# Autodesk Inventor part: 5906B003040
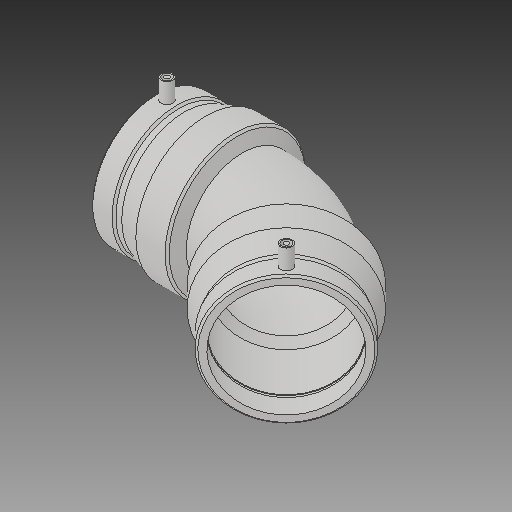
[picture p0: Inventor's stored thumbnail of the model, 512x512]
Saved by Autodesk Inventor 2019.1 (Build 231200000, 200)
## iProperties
Created: 2017-06
Part Number: 5906B003040
Material: Generic
Description: PLASSON 45° ELBOW 4''
Document SubType Name: Modeling
Designer: KIM
Mass: 55.0731 g
Surface Area: 148.067 cm^2
Volume: 55.0731 cm^3
Density: 1 g/cm^3
Appearance: Default
Author: KIM
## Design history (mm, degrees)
derived "5906B.ipt"
feature "Solid1::5906B.ipt"
tag "TaggingFeature1"
body "Solid1"
other parameters: "d_" = 114.1, "L_" = 271.78, "L_1" = 81.026, "D_" = 142.494, "A_" = 85.598, "d_2" = 12, "d2" = 142.494, "d4" = 67.945, "d5" = 128.2446, "d8" = 168 deg, "d10" = 32.4104, "d11" = 10.80347, "d14" = 17.6296, "d18" = 114.1, "d19" = 3.52592, "d20" = 168 deg, "d22" = 131.09448, "d23" = 142.494, "d24" = 127.16165, "d29" = 85.598, "d30" = 15, "d31" = 95.123, "d34" = 5 deg, "d35" = 12, "d39" = 0, "d41" = 4, "d42" = 14, "d43" = 0, "d44" = 9.6, "d45" = 4.8, "d46" = 6, "d47" = 0, "d49" = 114.1, "d50" = 96.985, "d51" = 32.4104, "d52" = 81.026, "d54" = 135 deg, "d65" = 114.1, "d67" = 45 deg, "d71" = 135 deg, "d75" = 7.1247, "d82" = 45 deg, "d83" = 81.026, "d84" = 128.2446, "d86" = 64.1223, "d87" = 135 deg, "d88" = 271.78, "d90" = 81.026, "d91" = 0, "d92" = 81.026, "d93" = 0, "d94" = 135 deg, "d95" = 63.58082, "d98" = 271.78, "d99" = 81.534, "d101" = 3, "d102" = 0, "d103" = 3, "d104" = 0, "d105" = 23.49754, "d106" = 5.87439
